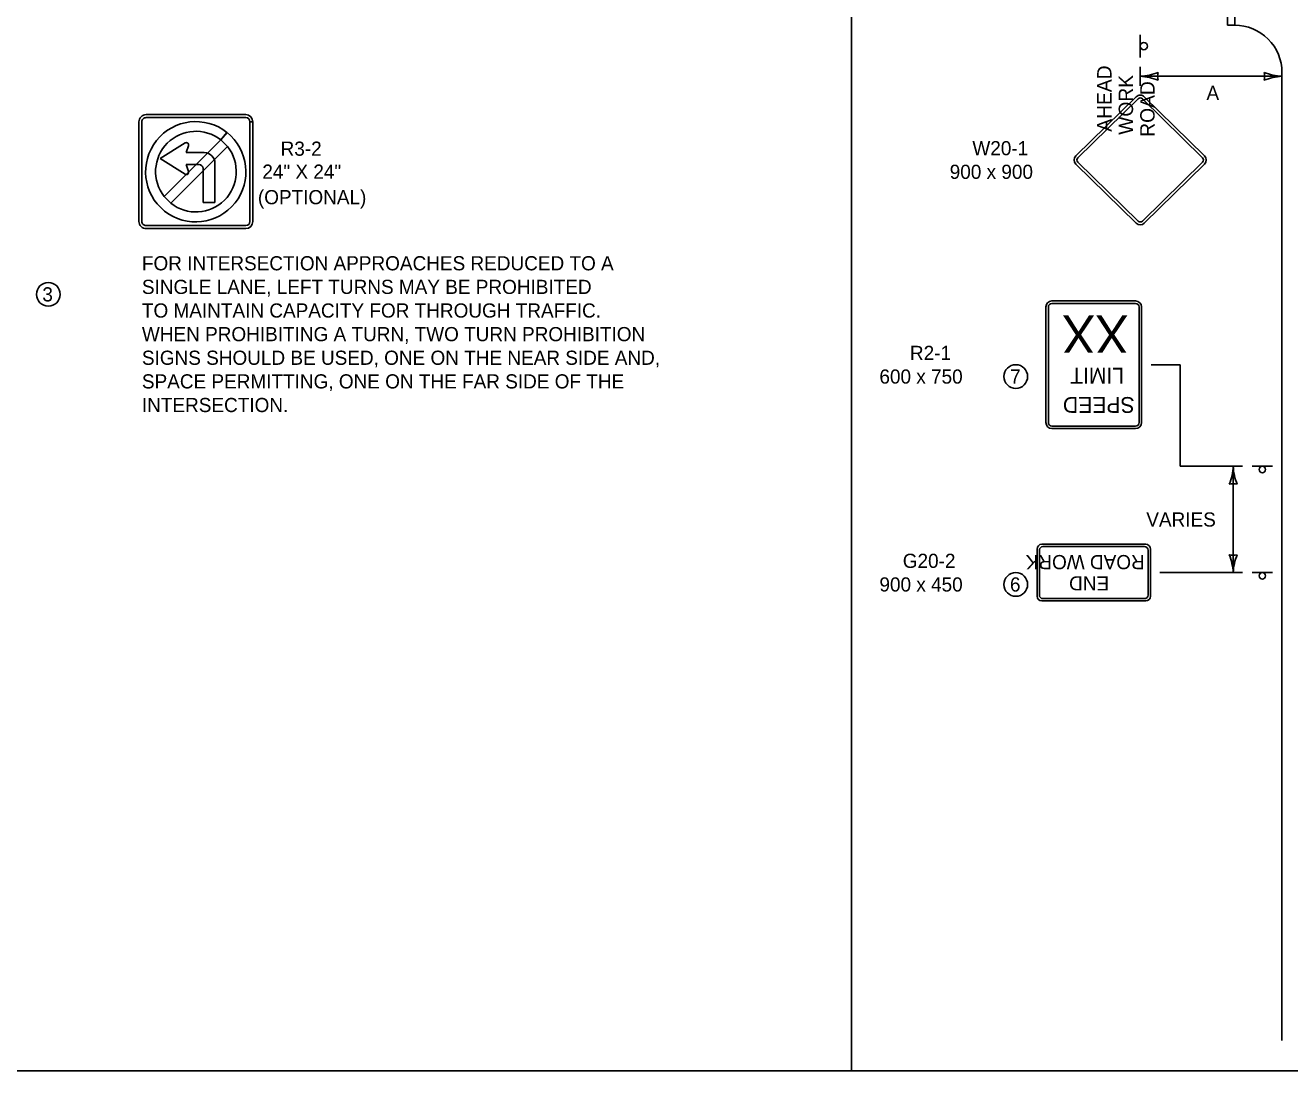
# Model space of a CAD drawing. Extents: x 49991.4 to 50021, y 49987.6 to 50011.4.
# Drawn here: x 50004.57 to 50009.92, y 49987.8 to 49992.22 of the extents above; entities that cross this region are included whole.
import ezdxf

# ---------------------------------------------------------------- set-up
doc = ezdxf.new("R2010")
doc.units = 0
for name, color, linetype in [('Level 1', 7, 'Continuous'), ('Level 2', 7, 'Continuous'), ('Level 25', 7, 'Continuous'), ('Level 3', 7, 'Continuous')]:
    doc.layers.add(name, color=color, linetype=linetype)

# ---------------------------------------------------------------- blocks, each defined once
blk = doc.blocks.new('R3.1')
at = {"layer": 'Level 25'}
for p, q in [((-35.82, 39.52), (38.27, 39.52)), ((-41.12, 34.23), (-38.91, 34.23)), ((-38.91, 34.23), (-41.12, 34.23)), ((-41.12, -39.86), (-41.12, 34.19)), ((-41.12, 34.19), (-38.91, 34.19)), ((-38.91, 34.19), (-38.91, -39.86)), ((38.27, 37.32), (-35.82, 37.32)), ((41.36, -39.86), (41.36, 34.23)), ((43.56, 34.23), (43.56, -39.86)), ((-17.34, 20.74), (-22.33, 15.75)), ((-17.34, 20.74), (-22.33, 15.75)), ((-21.92, 26.22), (-17.34, 20.74)), ((-17.22, 20.83), (-21.8, 26.31)), ((24.78, -21.38), (-17.34, 20.74)), ((-22.33, 15.75), (19.79, -26.37)), ((-4.9, 11.3), (8.36, 11.3)), ((8.36, 11.3), (6.72, 16.46)), ((9.31, 18.47), (27.68, 6.89)), ((9.31, 18.47), (9.31, 18.47)), ((-12.9, -25.75), (-12.9, 3.3)), ((8.36, 2.48), (-1.08, 2.48)), ((6.72, -2.69), (8.36, 2.48)), ((27.68, 6.89), (9.31, -4.7)), ((-4.08, -0.52), (-4.08, -25.75)), ((-4.08, -25.75), (-12.9, -25.75)), ((19.79, -26.37), (24.78, -21.38)), ((19.79, -26.37), (24.78, -21.38)), ((-35.82, -42.95), (38.27, -42.95)), ((38.27, -45.15), (-35.82, -45.15))]:
    blk.add_line(p, q, dxfattribs=at)
for centre, radius, start, end in [((-35.82, 34.23), 5.29, 90, 180), ((38.27, 34.23), 5.29, 0, 90), ((-35.82, 34.23), 3.09, 90, 180), ((1.33, -2.92), 37.27, 128.57303, 128.34072), ((38.27, 34.23), 3.09, 0, 90), ((1.22, -2.82), 29.99, 321.75713, 127.95466), ((1.22, -2.82), 29.99, 141.7565, 308.24287), ((-4.9, 3.3), 8, 90, 180), ((8.38, 16.99), 1.75, 57.75701, 197.61864), ((1.22, -2.82), 29.99, 44.28688, 44.41635), ((-1.08, -0.52), 3, 90, 180), ((8.38, -3.22), 1.75, 162.38039, 302.24384), ((1.22, -2.82), 29.99, 220.85636, 220.87145), ((-35.82, -39.86), 5.29, 180, 270), ((-35.82, -39.86), 3.09, 180, 270), ((38.27, -39.86), 5.29, 270, 0), ((38.27, -39.86), 3.09, 270, 0)]:
    blk.add_arc(centre, radius, start, end, dxfattribs=at)

msp = doc.modelspace()

# ---------------------------------------------------------------- linework, layer by layer
at = {"layer": 'Level 1'}
for p, q in [((50008.0668, 49998.9992), (50008.0668, 49987.7988)), ((50009.289, 49992.088), (50009.289, 49992.184)), ((50009.889, 49987.9261), (50009.889, 49992.024)), ((50009.0167, 49991.6709), (50009.272, 49991.921)), ((50009.0249, 49991.6626), (50009.2802, 49991.9127)), ((50009.298, 49991.9127), (50009.5532, 49991.6626)), ((50009.3062, 49991.921), (50009.5614, 49991.6709)), ((50009.2802, 49991.395), (50009.0249, 49991.6451)), ((50009.5532, 49991.6451), (50009.298, 49991.395)), ((50009.272, 49991.3866), (50009.0167, 49991.6367)), ((50009.5614, 49991.6367), (50009.3062, 49991.3866)), ((50008.915, 49991.0572), (50009.2694, 49991.0572)), ((50008.8896, 49990.5424), (50008.8896, 49991.0319)), ((50008.9002, 49990.5424), (50008.9002, 49991.0319)), ((50008.915, 49991.0466), (50009.2694, 49991.0466)), ((50009.2842, 49991.0319), (50009.2842, 49990.5424)), ((50009.2947, 49991.0319), (50009.2947, 49990.5424)), ((50009.2694, 49990.5277), (50008.915, 49990.5277)), ((50009.2694, 49990.5171), (50008.915, 49990.5171)), ((50009.0922, 49990.5171), (50009.0922, 49990.5171)), ((50009.7626, 49990.3571), (50009.849, 49990.3571)), ((50008.8521, 49989.8071), (50008.8521, 49990.0071)), ((50008.8621, 49989.8121), (50008.8621, 49990.0021)), ((50008.8722, 49990.0271), (50009.3122, 49990.0271)), ((50008.8771, 49990.0171), (50009.3071, 49990.0171)), ((50009.3221, 49990.0021), (50009.3221, 49989.8121)), ((50009.3321, 49990.0071), (50009.3321, 49989.8071)), ((50009.7626, 49989.9071), (50009.849, 49989.9071)), ((50008.8721, 49989.7871), (50009.3121, 49989.7871)), ((50008.8771, 49989.7971), (50009.3071, 49989.7971))]:
    msp.add_line(p, q, dxfattribs=at)
msp.add_lwpolyline([(49999.3835, 49998.9992), (50016.7501, 49998.9992), (50016.7501, 49987.7988), (49999.3835, 49987.7988)], close=True, dxfattribs=at)
msp.add_lwpolyline([(50009.659, 49992.224), (50009.689, 49992.224), (50009.689, 49992.5241), (50009.659, 49992.5241), (50009.659, 49992.224)], dxfattribs=at)
for centre, radius in [((50009.3042, 49992.136), 0.0152), ((50009.8059, 49990.3434), 0.0137), ((50009.8059, 49989.8934), 0.0137)]:
    msp.add_circle(centre, radius, dxfattribs=at)
for centre, radius, start, end in [((50009.689, 49992.024), 0.2, 359.9999, 90), ((50008.915, 49991.0319), 0.0253, 90, 180), ((50009.2694, 49991.0319), 0.0253, 360, 90), ((50008.915, 49991.0319), 0.0148, 90, 180), ((50009.2694, 49991.0319), 0.0148, 360, 90), ((50008.915, 49990.5424), 0.0253, 180, 270), ((50008.915, 49990.5424), 0.0148, 180, 270), ((50009.2694, 49990.5424), 0.0148, 270, 360), ((50009.2694, 49990.5424), 0.0253, 270, 360), ((50008.8722, 49990.0071), 0.02, 90, 180), ((50008.8771, 49990.0021), 0.015, 90, 180), ((50009.3071, 49990.0021), 0.015, 360, 90), ((50009.3122, 49990.0071), 0.02, 360, 90), ((50008.8721, 49989.8071), 0.02, 180, 270), ((50008.8771, 49989.8121), 0.015, 180, 270), ((50009.3071, 49989.8121), 0.015, 270, 360), ((50009.3121, 49989.8071), 0.02, 270, 360)]:
    msp.add_arc(centre, radius, start, end, dxfattribs=at)
for centre, major_axis, ratio, start_param, end_param in [((50009.289, 49991.904), (0.0243, 0), 0.98963, 0.785394, 2.356194), ((50009.289, 49991.904), (0.0126, 0), 0.98, 0.785394, 2.356194), ((50009.0338, 49991.6538), (-0.0243, 0), 0.98963, 5.497795, 7.068583), ((50009.0338, 49991.6538), (-0.0126, 0), 0.98, 5.497795, 7.068583), ((50009.5443, 49991.6538), (0.0126, 0), 0.98, 5.497787, 7.068583), ((50009.5443, 49991.6538), (0.0243, 0), 0.98963, 5.497787, 7.068583), ((50009.289, 49991.4037), (0.0243, 0), 0.98963, 3.926991, 5.497787), ((50009.289, 49991.4037), (0.0126, 0), 0.98, 3.926991, 5.497787)]:
    msp.add_ellipse(centre, major_axis=major_axis, ratio=ratio, start_param=start_param, end_param=end_param, dxfattribs=at)
at = {"layer": 'Level 2'}
for centre in [(50004.6667, 49991.0851), (50008.762, 49990.7372), (50008.762, 49989.8571)]:
    msp.add_circle(centre, 0.0501, dxfattribs=at)
at = {"layer": 'Level 3'}
for p, q in [((50009.289, 49991.968), (50009.289, 49992.048)), ((50009.289, 49992.008), (50009.889, 49992.008)), ((50009.3347, 49990.7872), (50009.4587, 49990.7872)), ((50009.4587, 49990.7872), (50009.4587, 49990.3571)), ((50009.4587, 49990.3571), (50009.7226, 49990.3571)), ((50009.6826, 49989.9071), (50009.6826, 49990.3571)), ((50009.3721, 49989.9071), (50009.7226, 49989.9071))]:
    msp.add_line(p, q, dxfattribs=at)
for centre, radius, start, end in [((50009.2775, 49992.2407), 0.233, 272.8273, 292.0772), ((50009.4172, 49992.008), 0.0548, 162.1388, 197.8612), ((50009.8982, 49992.2301), 0.2223, 247.456, 267.6395), ((50009.7608, 49992.008), 0.0548, 342.1388, 17.8612), ((50009.2799, 49991.7859), 0.2223, 67.456, 87.6395), ((50009.9005, 49991.7753), 0.233, 92.8273, 112.0772), ((50009.4605, 49990.3662), 0.2223, 337.456, 357.6395), ((50009.9153, 49990.3686), 0.233, 182.8273, 202.0772), ((50009.6826, 49990.2289), 0.0548, 72.1388, 107.8612), ((50009.6826, 49990.0353), 0.0548, 252.1388, 287.8612), ((50009.4499, 49989.8956), 0.233, 2.8273, 22.0772), ((50009.9048, 49989.8979), 0.2223, 157.456, 177.6395)]:
    msp.add_arc(centre, radius, start, end, dxfattribs=at)

# ---------------------------------------------------------------- block references
at = {"layer": 'Level 1', "xscale": 0.005696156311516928, "yscale": -0.0056961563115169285, "rotation": 179.9999999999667}
msp.add_blockref('R3.1', (50005.2985, 49991.6206), dxfattribs=at)

# ---------------------------------------------------------------- texts
at = {"layer": 'Level 1'}
for s, height, rotation, p in [('AHEAD', 0.06086, 90, (50009.1674, 49991.7736)), ('WORK', 0.06086, 90, (50009.2586, 49991.7606)), ('ROAD', 0.06086, 90, (50009.3499, 49991.7521)), ('XX', 0.15772, 180, (50009.2393, 49990.9961)), ('LIMIT', 0.06695, 180, (50009.2209, 49990.7741)), ('SPEED', 0.06695, 180, (50009.2653, 49990.6504)), ('ROAD WORK', 0.06, 180, (50009.3079, 49989.9817)), ('END', 0.06, 180, (50009.1573, 49989.8917))]:
    msp.add_text(s, height=height, rotation=rotation, dxfattribs=at).set_placement(p)
at = {"layer": 'Level 2'}
for s, p in [('A', (50009.5694, 49991.908)), ('W20-1', (50008.5785, 49991.6738)), ('900 x 900', (50008.4825, 49991.5738)), ('VARIES', (50009.3147, 49990.1021))]:
    msp.add_text(s, height=0.06, rotation=360, dxfattribs=at).set_placement(p)
for s, p in [('R3-2', (50005.65, 49991.6718)), ('24" X 24"', (50005.5727, 49991.5745)), ('(OPTIONAL)', (50005.5539, 49991.4665)), ('FOR INTERSECTION APPROACHES REDUCED TO A ', (50005.0629, 49991.1867)), ('3', (50004.6415, 49991.0551)), ('SINGLE LANE, LEFT TURNS MAY BE PROHIBITED ', (50005.0629, 49991.0867)), ('TO MAINTAIN CAPACITY FOR THROUGH TRAFFIC.', (50005.0629, 49990.9867)), ('WHEN PROHIBITING A TURN, TWO TURN PROHIBITION ', (50005.0629, 49990.8867)), ('SIGNS SHOULD BE USED, ONE ON THE NEAR SIDE AND,', (50005.0629, 49990.7867)), ('R2-1', (50008.3141, 49990.8072)), ('SPACE PERMITTING, ONE ON THE FAR SIDE OF THE', (50005.0629, 49990.6867)), ('600 x 750', (50008.1849, 49990.7072)), ('7', (50008.7382, 49990.7072)), ('INTERSECTION.', (50005.0629, 49990.5867)), ('G20-2', (50008.2838, 49989.9271)), ('900 x 450', (50008.185, 49989.8271)), ('6', (50008.7375, 49989.8271))]:
    msp.add_text(s, height=0.06, dxfattribs=at).set_placement(p)

doc.saveas('drawing.dxf')
